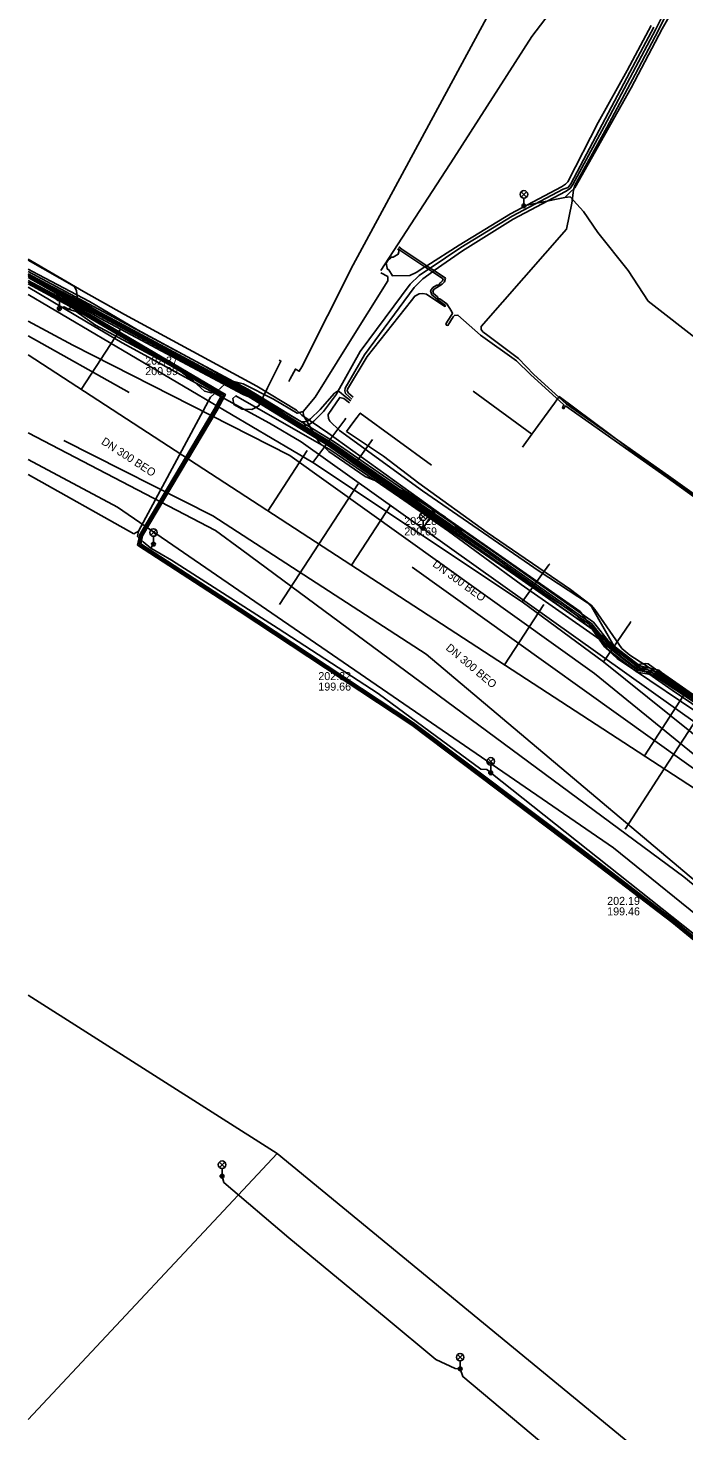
# Model space of a CAD drawing. Extents: x -598932 to -598196, y -1162210 to -1161504.
# Drawn here: x -598932 to -598866.4, y -1161789 to -1161648.7 of the extents above; entities that cross this region are included whole.
import ezdxf

# ---------------------------------------------------------------- set-up
doc = ezdxf.new("R2010")
doc.units = 0
for name, color, linetype in [('Vrstva 1', 7, 'Continuous'), ('Vrstva 12', 7, 'Continuous'), ('Vrstva 13', 7, 'Continuous'), ('Vrstva 14', 7, 'Continuous'), ('Vrstva 16', 7, 'Continuous'), ('Vrstva 19', 7, 'Continuous'), ('Vrstva 33', 7, 'Continuous'), ('Vrstva 4', 7, 'Continuous'), ('Vrstva 42', 7, 'Continuous'), ('Vrstva 44', 7, 'Continuous'), ('Vrstva 55', 7, 'Continuous'), ('Vrstva 58', 7, 'Continuous'), ('Vrstva 9', 7, 'Continuous')]:
    doc.layers.add(name, color=color, linetype=linetype)

msp = doc.modelspace()

# ---------------------------------------------------------------- linework, layer by layer
at = {"layer": 'Vrstva 1'}
for p, q in [((-598921.912, -1161685.148), (-598932.017, -1161679.474)), ((-598892.23, -1161711.3), (-598864.64, -1161734.54))]:
    msp.add_line(p, q, dxfattribs=at)
for points in [[(-598928.43, -1161689.95), (-598913.55, -1161697.462), (-598892.23, -1161711.3)], [(-598893.601, -1161702.614), (-598862.803, -1161724.661), (-598852.066, -1161734.061)]]:
    msp.add_lwpolyline(points, dxfattribs=at)
at = {"layer": 'Vrstva 12'}
for points in [[(-598899.12, -1161687.61), (-598899.44, -1161688.02), (-598900.17, -1161689.03)], [(-598899.12, -1161687.61), (-598898.8, -1161687.19), (-598891.67, -1161692.41)], [(-598900.17, -1161689.03), (-598896.49, -1161691.49), (-598892.96, -1161694.19), (-598886.1, -1161699.15)], [(-598886.1, -1161699.15), (-598877.79, -1161704.85), (-598875.68, -1161706.42), (-598875.36, -1161706.84), (-598872.64, -1161710.75), (-598871.85, -1161711.4), (-598865.87, -1161715.26), (-598859.85, -1161719.44), (-598857.82, -1161720.91)]]:
    msp.add_lwpolyline(points, dxfattribs=at)
at = {"layer": 'Vrstva 13'}
for p, q in [((-598881.65, -1161689.29), (-598887.53, -1161685)), ((-598879.4, -1161686.2), (-598881.65, -1161689.29)), ((-598881.65, -1161689.29), (-598882.6, -1161690.59)), ((-598860.02, -1161699.34), (-598868.99, -1161692.92))]:
    msp.add_line(p, q, dxfattribs=at)
msp.add_lwpolyline([(-598868.99, -1161692.92), (-598878.91, -1161685.54), (-598879.4, -1161686.2)], dxfattribs=at)
at = {"layer": 'Vrstva 14'}
for points in [[(-598905.96, -1161684.02), (-598905.81, -1161683.76), (-598905.28, -1161682.79), (-598904.9, -1161683.01), (-598904.66, -1161682.57), (-598899.53, -1161672.38), (-598885.71, -1161646.83), (-598913.59, -1161631.66), (-598913.82, -1161630.19), (-598915, -1161629.5), (-598914.03, -1161627.64)], [(-598922.595, -1161680.155), (-598926.19, -1161678.08), (-598932.017, -1161674.61)], [(-598829.54, -1161748.41), (-598830.18, -1161747.833), (-598837.775, -1161740.986), (-598852.077, -1161728.091), (-598854.47, -1161725.935), (-598854.596, -1161725.824), (-598854.898, -1161725.553), (-598904.716, -1161690.077), (-598907.876, -1161688.204), (-598922.595, -1161680.155)], [(-598932.017, -1161691.842), (-598923.09, -1161696.61), (-598873.47, -1161730.66), (-598862.84, -1161739.26), (-598845.42, -1161753.81), (-598843.777, -1161755.473), (-598775.893, -1161819.626), (-598773.362, -1161822.181), (-598772.235, -1161823.459), (-598713.72, -1161886.81), (-598709.736, -1161891.092), (-598695.338, -1161905.651)]]:
    msp.add_lwpolyline(points, dxfattribs=at)
at = {"layer": 'Vrstva 16'}
for points in [[(-598823.373, -1161756.543), (-598824.813, -1161755.083), (-598825.101, -1161754.79), (-598825.418, -1161754.469), (-598832.06, -1161748.07), (-598837.71, -1161742.83), (-598854.7, -1161728), (-598856.9, -1161726.21), (-598874.5, -1161712.08), (-598882.61, -1161706.08), (-598903.54, -1161692.14), (-598932.017, -1161675.35)], [(-598903.54, -1161692.14), (-598900.36, -1161687.86), (-598900.24, -1161687.71)], [(-598882.61, -1161706.08), (-598879.94, -1161702.38), (-598879.85, -1161702.26)], [(-598874.5, -1161712.08), (-598871.83, -1161708.17), (-598871.75, -1161708.05)]]:
    msp.add_lwpolyline(points, dxfattribs=at)
at = {"layer": 'Vrstva 19'}
msp.add_lwpolyline([(-598825.074, -1161756.558), (-598825.698, -1161755.986), (-598825.873, -1161755.832), (-598826.048, -1161755.671), (-598826.225, -1161755.508), (-598856.03, -1161729), (-598875.4, -1161713.22), (-598905.83, -1161691.44), (-598927.55, -1161680.41), (-598932.017, -1161677.987)], dxfattribs=at)
at = {"layer": 'Vrstva 33'}
for p, q in [((-598882.706, -1161665.062), (-598882.176, -1161665.592)), ((-598882.706, -1161665.592), (-598882.176, -1161665.062)), ((-598882.441, -1161666.477), (-598882.441, -1161665.702)), ((-598929.155, -1161675.335), (-598928.625, -1161675.865)), ((-598929.155, -1161675.865), (-598928.625, -1161675.335)), ((-598928.89, -1161676.75), (-598928.89, -1161675.975)), ((-598892.765, -1161697.285), (-598892.235, -1161697.815)), ((-598892.765, -1161697.815), (-598892.235, -1161697.285)), ((-598919.745, -1161698.875), (-598919.215, -1161699.405)), ((-598919.745, -1161699.405), (-598919.215, -1161698.875)), ((-598892.5, -1161698.7), (-598892.5, -1161697.925)), ((-598919.48, -1161700.29), (-598919.48, -1161699.515)), ((-598886.025, -1161721.755), (-598885.495, -1161722.285)), ((-598886.025, -1161722.285), (-598885.495, -1161721.755)), ((-598885.76, -1161723.17), (-598885.76, -1161722.395)), ((-598912.885, -1161762.085), (-598912.355, -1161762.615)), ((-598912.885, -1161762.615), (-598912.355, -1161762.085)), ((-598912.62, -1161763.5), (-598912.62, -1161762.725)), ((-598889.085, -1161781.335), (-598888.555, -1161781.865)), ((-598889.085, -1161781.865), (-598888.555, -1161781.335)), ((-598888.82, -1161782.75), (-598888.82, -1161781.975))]:
    msp.add_line(p, q, dxfattribs=at)
for centre, radius in [((-598882.441, -1161665.327), 0.375), ((-598882.441, -1161666.477), 0.19), ((-598882.441, -1161666.477), 0.05), ((-598928.89, -1161675.6), 0.375), ((-598928.89, -1161676.75), 0.19), ((-598928.89, -1161676.75), 0.05), ((-598892.5, -1161697.55), 0.375), ((-598919.48, -1161699.14), 0.375), ((-598892.5, -1161698.7), 0.19), ((-598892.5, -1161698.7), 0.05), ((-598919.48, -1161700.29), 0.19), ((-598919.48, -1161700.29), 0.05), ((-598885.76, -1161722.02), 0.375), ((-598885.76, -1161723.17), 0.19), ((-598885.76, -1161723.17), 0.05), ((-598912.62, -1161762.35), 0.375), ((-598912.62, -1161763.5), 0.19), ((-598912.62, -1161763.5), 0.05), ((-598888.82, -1161781.6), 0.375), ((-598888.82, -1161782.75), 0.19), ((-598888.82, -1161782.75), 0.05)]:
    msp.add_circle(centre, radius, dxfattribs=at)
at = {"layer": 'Vrstva 42'}
for points in [[(-598864.45, -1161639.16), (-598869.241, -1161648.817), (-598871.546, -1161653.138), (-598874.425, -1161658.526), (-598877.55, -1161664.34), (-598877.82, -1161664.75), (-598878.28, -1161665.03), (-598883.51, -1161667.79), (-598888.59, -1161670.96), (-598891.413, -1161672.951), (-598891.588, -1161673.075), (-598892.56, -1161673.76), (-598893.43, -1161674.65), (-598898.37, -1161681.37), (-598900.32, -1161684.69), (-598900.36, -1161684.98), (-598900.29, -1161685.22), (-598899.64, -1161685.795)], [(-598864.22, -1161639.31), (-598868.99, -1161648.92), (-598871.327, -1161653.34), (-598874.16, -1161658.64), (-598877.36, -1161664.45), (-598877.49, -1161664.89), (-598877.65, -1161666.19), (-598878.19, -1161668.81), (-598886.7, -1161678.52), (-598886.7, -1161678.83), (-598886.55, -1161679.06), (-598886.04, -1161679.44), (-598882.98, -1161681.72), (-598881.456, -1161683.335), (-598878.23, -1161686.26), (-598872.71, -1161690.14), (-598867.98, -1161693.46), (-598863.2, -1161696.89)], [(-598869.46, -1161648.615), (-598871.866, -1161653.121), (-598874.63, -1161658.33), (-598877.74, -1161664.26), (-598878.02, -1161664.63), (-598878.53, -1161664.8), (-598883.63, -1161667.51), (-598888.76, -1161670.64), (-598891.803, -1161672.691), (-598891.983, -1161672.812), (-598892.9, -1161673.43), (-598893.83, -1161674.3), (-598898.83, -1161681.04), (-598901.034, -1161685.029), (-598901.19, -1161685.31), (-598902.48, -1161687.03), (-598903.46, -1161688), (-598903.9, -1161688.35), (-598904.34, -1161688.43), (-598904.92, -1161688.42), (-598914.54, -1161682.8), (-598921.26, -1161679.26), (-598926.12, -1161676.38), (-598931.18, -1161673.74), (-598932.017, -1161673.304)], [(-598869.71, -1161648.43), (-598872.135, -1161652.953), (-598875.02, -1161658.13), (-598878.05, -1161664.06), (-598878.27, -1161664.29), (-598878.67, -1161664.58), (-598883.79, -1161667.27), (-598888.93, -1161670.4), (-598892.155, -1161672.457), (-598892.339, -1161672.574), (-598893.21, -1161673.13), (-598893.84, -1161673.42), (-598895.579, -1161673.483), (-598895.96, -1161672.88), (-598896.071, -1161672.813), (-598896.112, -1161672.711), (-598896.205, -1161672.219), (-598895.97, -1161671.828), (-598895.806, -1161671.753), (-598895.71, -1161671.6)], [(-598895.085, -1161670.794), (-598894.938, -1161670.924), (-598894.962, -1161671.061), (-598895.023, -1161671.304), (-598895.519, -1161671.602), (-598895.71, -1161671.6)], [(-598895.044, -1161670.725), (-598894.76, -1161670.96), (-598892.339, -1161672.574), (-598891.983, -1161672.812), (-598891.588, -1161673.075), (-598890.524, -1161673.784), (-598890.57, -1161673.969), (-598890.743, -1161674.141), (-598890.856, -1161674.213), (-598890.95, -1161674.39)], [(-598894.936, -1161670.555), (-598894.64, -1161670.8), (-598892.155, -1161672.457), (-598891.803, -1161672.691), (-598891.413, -1161672.951), (-598890.296, -1161673.696), (-598890.39, -1161674.071), (-598890.617, -1161674.299), (-598890.897, -1161674.475), (-598891.417, -1161674.793), (-598891.552, -1161675.014), (-598891.483, -1161675.252), (-598891.084, -1161675.58), (-598891.01, -1161675.77)], [(-598932.017, -1161672.81), (-598931.01, -1161673.33), (-598925.88, -1161676.05), (-598921.09, -1161678.87), (-598914.41, -1161682.47), (-598904.67, -1161688.07), (-598904.37, -1161688.07), (-598904.08, -1161688), (-598903.79, -1161687.78), (-598902.8, -1161686.85), (-598901.37, -1161685.21), (-598901.09, -1161685.01), (-598901.034, -1161685.029), (-598900.892, -1161685.076), (-598900.709, -1161685.218), (-598900.47, -1161685.386), (-598899.753, -1161685.976)], [(-598932.017, -1161673.922), (-598927.716, -1161676.239), (-598912.291, -1161685.333), (-598913.149, -1161686.963), (-598920.569, -1161699.456), (-598920.751, -1161700.261), (-598910.738, -1161706.755), (-598893.483, -1161718.167), (-598876.589, -1161730.881), (-598867.477, -1161737.872), (-598856.444, -1161746.915), (-598838.797, -1161762.111), (-598820.961, -1161780.547), (-598809.359, -1161793.3), (-598752.857, -1161856.721), (-598745.208, -1161865.511), (-598726.323, -1161886.484), (-598722.413, -1161888.903), (-598722.054, -1161888.564)], [(-598932.017, -1161673.922), (-598927.716, -1161676.239), (-598912.291, -1161685.333), (-598913.149, -1161686.963), (-598920.569, -1161699.456), (-598920.751, -1161700.261), (-598910.738, -1161706.755), (-598893.483, -1161718.167), (-598876.589, -1161730.881), (-598867.477, -1161737.872), (-598856.444, -1161746.915), (-598838.797, -1161762.111), (-598820.961, -1161780.547), (-598809.359, -1161793.3), (-598752.857, -1161856.721), (-598745.208, -1161865.511), (-598726.323, -1161886.484), (-598722.413, -1161888.903), (-598722.053, -1161888.563)], [(-598722.546, -1161888.247), (-598722.93, -1161888.76), (-598726.42, -1161886.6), (-598745.32, -1161865.61), (-598752.97, -1161856.82), (-598791.34, -1161813.75), (-598809.47, -1161793.4), (-598821.07, -1161780.65), (-598838.9, -1161762.22), (-598856.54, -1161747.03), (-598867.57, -1161737.99), (-598876.68, -1161731), (-598893.57, -1161718.29), (-598910.82, -1161706.88), (-598920.92, -1161700.33), (-598920.71, -1161699.4), (-598913.28, -1161686.89), (-598912.49, -1161685.39), (-598927.79, -1161676.37), (-598932.017, -1161674.093)], [(-598722.486, -1161888.162), (-598723.009, -1161888.888), (-598726.517, -1161886.716), (-598745.432, -1161865.709), (-598753.083, -1161856.919), (-598809.581, -1161793.5), (-598821.179, -1161780.753), (-598839.003, -1161762.329), (-598856.636, -1161747.145), (-598867.663, -1161738.108), (-598876.771, -1161731.119), (-598893.657, -1161718.413), (-598910.902, -1161707.005), (-598921.089, -1161700.399), (-598920.851, -1161699.344), (-598913.411, -1161686.817), (-598912.689, -1161685.447), (-598927.864, -1161676.501), (-598932.017, -1161674.264)], [(-598722.486, -1161888.162), (-598723.009, -1161888.888), (-598726.517, -1161886.716), (-598745.432, -1161865.709), (-598753.083, -1161856.919), (-598809.581, -1161793.5), (-598821.179, -1161780.753), (-598839.003, -1161762.329), (-598856.636, -1161747.145), (-598867.663, -1161738.108), (-598876.771, -1161731.119), (-598893.657, -1161718.413), (-598910.902, -1161707.005), (-598921.089, -1161700.399), (-598920.851, -1161699.344), (-598913.411, -1161686.817), (-598912.689, -1161685.447), (-598927.864, -1161676.501), (-598932.017, -1161674.264)], [(-598890.95, -1161674.39), (-598891.141, -1161674.389), (-598891.563, -1161674.647), (-598891.768, -1161674.986), (-598891.657, -1161675.368), (-598891.069, -1161675.85), (-598890.269, -1161676.44), (-598890.338, -1161676.523), (-598892.18, -1161675.29), (-598892.56, -1161675.23), (-598892.93, -1161675.26), (-598893.36, -1161675.49), (-598893.67, -1161675.93), (-598898.12, -1161681.55), (-598900.07, -1161684.81), (-598900.11, -1161684.98), (-598899.983, -1161685.197), (-598899.528, -1161685.617)], [(-598863.46, -1161697), (-598868.11, -1161693.62), (-598872.84, -1161690.3), (-598878.28, -1161686.47), (-598878.447, -1161686.742), (-598878.541, -1161686.724), (-598878.575, -1161686.647), (-598878.45, -1161686.37), (-598881.78, -1161683.34), (-598883.2, -1161681.96), (-598886.79, -1161679.39), (-598889.04, -1161677.39), (-598889.396, -1161677.423), (-598889.516, -1161677.585), (-598890.045, -1161678.43), (-598890.196, -1161678.403), (-598890.258, -1161678.268), (-598889.703, -1161677.431), (-598889.592, -1161677.235), (-598889.68, -1161677.004), (-598890.151, -1161676.279), (-598890.833, -1161675.776), (-598891.01, -1161675.77)], [(-598899.87, -1161686.159), (-598900.439, -1161685.752), (-598900.851, -1161685.63), (-598902.02, -1161687.35), (-598902.01, -1161687.38), (-598901.98, -1161687.75), (-598901.86, -1161687.99), (-598900.87, -1161688.95), (-598892.57, -1161694.96), (-598880.93, -1161703.01), (-598876.09, -1161706.17), (-598875.64, -1161706.61), (-598873.33, -1161710.7), (-598873.16, -1161710.98), (-598871.43, -1161712.22), (-598871.03, -1161712.32), (-598870.32, -1161712.22), (-598870.02, -1161712.28), (-598868.28, -1161713.55), (-598863.7, -1161716.69)]]:
    msp.add_lwpolyline(points, dxfattribs=at)
at = {"layer": 'Vrstva 44'}
for points in [[(-598932.017, -1161673.408), (-598909.891, -1161685.303), (-598901.626, -1161690.266), (-598886.522, -1161700.808), (-598875.468, -1161708.648), (-598874.227, -1161710.421), (-598871.048, -1161712.926), (-598869.131, -1161713.245), (-598856.98, -1161721.803)], [(-598932.017, -1161673.635), (-598909.989, -1161685.477), (-598901.734, -1161690.434), (-598886.638, -1161700.972), (-598875.612, -1161708.792), (-598874.373, -1161710.559), (-598871.132, -1161713.114), (-598869.209, -1161713.435), (-598857.08, -1161721.977)]]:
    msp.add_lwpolyline(points, dxfattribs=at)
at = {"layer": 'Vrstva 55'}
msp.add_line((-598921.431, -1161699.254), (-598932.017, -1161693.351), dxfattribs=at)
for points in [[(-598824.456, -1161626.163), (-598829.808, -1161624.779), (-598830.554, -1161627.348), (-598833.454, -1161633.73), (-598834.449, -1161634.476), (-598836.314, -1161634.89), (-598841.701, -1161634.352), (-598846.053, -1161634.352), (-598851.274, -1161633.606), (-598852.144, -1161632.031), (-598854.82, -1161631.35), (-598856.496, -1161631.285), (-598859.106, -1161631.865), (-598861.45, -1161628.143), (-598868.133, -1161633.786), (-598876.448, -1161642.695), (-598881.645, -1161649.526), (-598889.446, -1161661.697), (-598896.738, -1161672.921)], [(-598863.169, -1161639.186), (-598868.616, -1161648.784), (-598871.713, -1161654.674), (-598877.344, -1161664.656), (-598877.845, -1161665.132), (-598878.341, -1161665.634), (-598880.641, -1161666.108), (-598882.441, -1161666.477), (-598880.641, -1161666.108), (-598878.341, -1161665.634), (-598877.818, -1161665.583), (-598876.497, -1161667.046), (-598875.056, -1161669.126), (-598872.029, -1161672.945), (-598870.02, -1161675.998), (-598864.758, -1161680.105)], [(-598932.017, -1161671.889), (-598927.37, -1161674.54), (-598927.19, -1161674.97), (-598927.1, -1161675.61), (-598927.57, -1161676.55), (-598928.02, -1161676.81), (-598928.42, -1161676.57), (-598928.89, -1161676.75), (-598928.42, -1161676.57), (-598928.02, -1161676.81), (-598927.22, -1161677.02), (-598925.28, -1161678.39), (-598917.02, -1161682.84), (-598915.48, -1161684.01), (-598914.37, -1161684.99), (-598913.72, -1161685.17), (-598913.09, -1161684.98), (-598912.36, -1161684.29), (-598911.46, -1161684.05), (-598910.52, -1161684.27), (-598907.49, -1161685.8), (-598905.11, -1161687.21), (-598904.5, -1161687.05), (-598903.31, -1161685.61), (-598900, -1161680.291), (-598896.06, -1161673.96), (-598896.05, -1161673.54), (-598896.75, -1161673.16)], [(-598896.75, -1161673.16), (-598896.05, -1161673.54), (-598896.06, -1161673.96), (-598900, -1161680.291), (-598903.31, -1161685.61), (-598904.5, -1161687.05), (-598905.11, -1161687.21), (-598907.49, -1161685.8), (-598910.52, -1161684.27), (-598911.46, -1161684.05), (-598912.36, -1161684.29), (-598913.09, -1161684.98), (-598913.79, -1161685.59), (-598920.99, -1161699), (-598921.431, -1161699.254)], [(-598896.75, -1161673.16), (-598896.05, -1161673.54), (-598896.06, -1161673.96), (-598900, -1161680.291), (-598903.31, -1161685.61), (-598904.5, -1161687.05), (-598905.11, -1161687.21), (-598907.49, -1161685.8), (-598910.52, -1161684.27), (-598911.46, -1161684.05), (-598912.36, -1161684.29), (-598913.09, -1161684.98), (-598913.79, -1161685.59), (-598920.99, -1161699), (-598921.06, -1161699.53), (-598920.59, -1161700), (-598920.51, -1161700.08), (-598919.75, -1161700.7), (-598919.48, -1161700.29), (-598919.75, -1161700.7), (-598917.66, -1161701.91), (-598907.02, -1161708.74), (-598897.03, -1161715.25), (-598886.76, -1161722.79), (-598886.16, -1161722.84), (-598885.76, -1161723.17)], [(-598896.75, -1161673.16), (-598896.05, -1161673.54), (-598896.06, -1161673.96), (-598900, -1161680.291), (-598903.31, -1161685.61), (-598904.5, -1161687.05), (-598904.48, -1161687.45), (-598902.95, -1161690.07), (-598901.94, -1161691.03), (-598898.33, -1161693.55), (-598897.5, -1161693.88), (-598895.73, -1161694.44), (-598894.23, -1161695.17), (-598891.57, -1161696.8), (-598891.56, -1161697.16), (-598892.5, -1161698.7), (-598891.56, -1161697.16), (-598891.23, -1161697.01), (-598890.29, -1161697.59), (-598888.38, -1161699.3), (-598887.464, -1161700), (-598881.85, -1161704.29), (-598877.64, -1161707.05), (-598876.08, -1161708.44), (-598874.77, -1161709.32), (-598872.98, -1161710.9), (-598871.11, -1161712.3), (-598870.15, -1161712.8), (-598866.59, -1161715.18), (-598865.98, -1161715.76)], [(-598885.76, -1161723.17), (-598852.64, -1161749.45), (-598827.15, -1161770.07), (-598815.83, -1161780.75), (-598802.91, -1161792.53), (-598792.55, -1161802.078), (-598793.7, -1161803.05)], [(-598868.736, -1161800.66), (-598868.8, -1161800.47), (-598868.942, -1161800.444), (-598871.88, -1161797.35), (-598878.83, -1161791.68), (-598888.54, -1161783.53), (-598888.83, -1161782.76), (-598889.31, -1161782.74), (-598891.26, -1161781.82), (-598896.22, -1161777.68), (-598905.94, -1161769.65), (-598912.46, -1161764.12), (-598912.62, -1161763.5)]]:
    msp.add_lwpolyline(points, dxfattribs=at)
at = {"layer": 'Vrstva 58'}
for points in [[(-598854.83, -1161724.47), (-598856.6, -1161723.03), (-598863.41, -1161718.27), (-598873.13, -1161711.72), (-598874.07, -1161710.85), (-598876.83, -1161707.02), (-598890.39, -1161697.57), (-598891.22, -1161696.97), (-598902.04, -1161689.16), (-598904.65, -1161687.39), (-598905.17, -1161686.9), (-598909.13, -1161684.5), (-598922.36, -1161677.33), (-598926.46, -1161675.04), (-598932.017, -1161671.816)], [(-598932.017, -1161673.048), (-598910.041, -1161684.816), (-598901.421, -1161690.062), (-598886.196, -1161700.576), (-598875.501, -1161708.113), (-598873.869, -1161710.176), (-598870.843, -1161712.475), (-598868.959, -1161712.906), (-598868.699, -1161713.121), (-598856.77, -1161721.456), (-598855.01, -1161722.26), (-598836.865, -1161738.142), (-598836.102, -1161738.864), (-598835.201, -1161740.376), (-598827.833, -1161747.695), (-598826.3, -1161748.441), (-598823.685, -1161750.664), (-598815.491, -1161756.899), (-598814.153, -1161757.868)], [(-598932.017, -1161673.274), (-598910.14, -1161684.99), (-598901.53, -1161690.23), (-598886.31, -1161700.74), (-598875.64, -1161708.26), (-598874.01, -1161710.32), (-598870.93, -1161712.66), (-598869.05, -1161713.09), (-598868.82, -1161713.28), (-598856.87, -1161721.63)], [(-598932.017, -1161673.501), (-598910.239, -1161685.164), (-598901.639, -1161690.398), (-598886.424, -1161700.904), (-598875.779, -1161708.407), (-598874.151, -1161710.464), (-598871.017, -1161712.845), (-598869.141, -1161713.274), (-598868.941, -1161713.439), (-598856.97, -1161721.804), (-598855.23, -1161722.6), (-598837.135, -1161738.438), (-598836.418, -1161739.116), (-598835.519, -1161740.624), (-598828.067, -1161748.025), (-598826.52, -1161748.779), (-598823.935, -1161750.976), (-598815.729, -1161757.221), (-598814.307, -1161758.252), (-598813.04, -1161758.422), (-598811.744, -1161758.253)], [(-598932.017, -1161673.501), (-598910.239, -1161685.164), (-598901.639, -1161690.398), (-598886.424, -1161700.904), (-598875.779, -1161708.407), (-598874.151, -1161710.464), (-598871.017, -1161712.845), (-598869.141, -1161713.274), (-598868.941, -1161713.439), (-598856.97, -1161721.804), (-598855.23, -1161722.6), (-598837.135, -1161738.438), (-598836.418, -1161739.116), (-598835.519, -1161740.624), (-598828.067, -1161748.025), (-598826.52, -1161748.779), (-598823.935, -1161750.976), (-598815.729, -1161757.221), (-598814.307, -1161758.252), (-598813.04, -1161758.422), (-598811.744, -1161758.253)], [(-598910.5, -1161685.33), (-598924.78, -1161677.72), (-598932.017, -1161673.633)], [(-598906.92, -1161681.9), (-598906.73, -1161682), (-598908.07, -1161684.68), (-598908.96, -1161686.46), (-598909.66, -1161686.85), (-598910.62, -1161686.81), (-598911.44, -1161686.34), (-598911.54, -1161685.75), (-598911.24, -1161685.48), (-598901.76, -1161690.91), (-598894.88, -1161695.6), (-598889.99, -1161699), (-598882.71, -1161704.32), (-598875.2, -1161709.61), (-598867.61, -1161714.89), (-598862.64, -1161718.26), (-598856.89, -1161722.68), (-598847.53, -1161730.74), (-598826.36, -1161749.84), (-598821.93, -1161753.63), (-598818.09, -1161757.31), (-598817.47, -1161757.65)], [(-598815.57, -1161757.946), (-598816.564, -1161756.821), (-598822.29, -1161752.46), (-598826.7, -1161748.67), (-598835.57, -1161740.87), (-598837.06, -1161738.59), (-598845.42, -1161731.19), (-598855.61, -1161722.93), (-598861.19, -1161718.9), (-598869.25, -1161713.56), (-598871.02, -1161712.63), (-598875.52, -1161708.87), (-598883.3, -1161703.42), (-598891.84, -1161697.55), (-598902.07, -1161690.39), (-598909.96, -1161685.58), (-598910.5, -1161685.33)], [(-598899.302, -1161692.242), (-598899.17, -1161692.08), (-598898.24, -1161690.76), (-598897.58, -1161689.83)]]:
    msp.add_lwpolyline(points, dxfattribs=at)
at = {"layer": 'Vrstva 9'}
for p, q in [((-598926.695, -1161684.844), (-598922.769, -1161678.81)), ((-598932.017, -1161681.381), (-598863.01, -1161726.284)), ((-598932.017, -1161689.176), (-598913.268, -1161698.946)), ((-598908.037, -1161696.985), (-598904.111, -1161690.951)), ((-598902.949, -1161700.296), (-598899.023, -1161694.262)), ((-598899.689, -1161702.417), (-598895.763, -1161696.383)), ((-598906.867, -1161706.335), (-598902.941, -1161700.301)), ((-598884.375, -1161712.382), (-598880.449, -1161706.348)), ((-598870.403, -1161721.474), (-598866.477, -1161715.44)), ((-598868.408, -1161722.772), (-598864.482, -1161716.738)), ((-598872.334, -1161728.806), (-598868.408, -1161722.772)), ((-598932.017, -1161745.401), (-598907.124, -1161761.224)), ((-598932.017, -1161787.821), (-598907.124, -1161761.224)), ((-598907.124, -1161761.224), (-598870.923, -1161791.006))]:
    msp.add_line(p, q, dxfattribs=at)
msp.add_lwpolyline([(-598913.268, -1161698.946), (-598910.65, -1161700.86), (-598866.44, -1161733.56), (-598852.175, -1161745.288)], dxfattribs=at)

# ---------------------------------------------------------------- texts
at = {"layer": 'Vrstva 4'}
for s, p in [('202.37', (-598920.3, -1161682.349)), ('200.99', (-598920.3, -1161683.399)), ('202.28', (-598894.402, -1161698.376)), ('200.69', (-598894.402, -1161699.426)), ('202.32', (-598902.995, -1161713.894)), ('199.66', (-598902.995, -1161714.944)), ('202.19', (-598874.116, -1161736.37)), ('199.46', (-598874.116, -1161737.42))]:
    msp.add_text(s, height=0.8, dxfattribs=at).set_placement(p)
for rotation, p in [(327, (-598924.767, -1161690.228)), (324, (-598891.64, -1161702.456)), (320, (-598890.32, -1161710.79))]:
    msp.add_text('DN 300 BEO', height=0.8, rotation=rotation, dxfattribs=at).set_placement(p)

doc.saveas('drawing.dxf')
